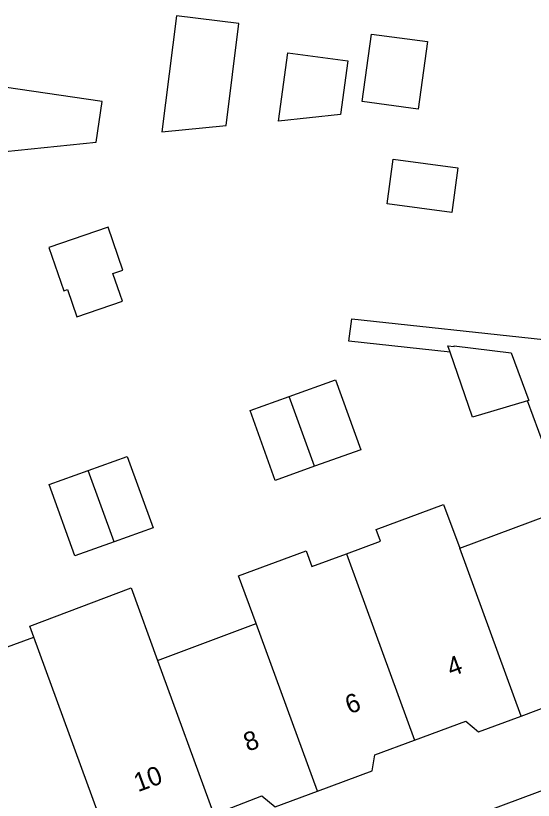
# Model space of a CAD drawing. Extents: x 161258 to 161838, y 380836 to 381727.
# Drawn here: x 161670.25 to 161697.93, y 381501.61 to 381543.54 of the extents above; entities that cross this region are included whole.
import ezdxf

# ---------------------------------------------------------------- set-up
doc = ezdxf.new("R2010")
doc.units = 0
for name, color, linetype in [('IMGEO_Pand', 7, 'Continuous'), ('IMGEO_Pand_nummerreeks', 7, 'Continuous'), ('IMGEO_Voetpad_open', 7, 'Continuous')]:
    doc.layers.add(name, color=color, linetype=linetype)

msp = doc.modelspace()

# ---------------------------------------------------------------- linework, layer by layer
at = {"layer": 'IMGEO_Pand'}
for points in [[(161682.189, 381543.121), (161678.843, 381543.541), (161678.064, 381537.338), (161681.504, 381537.668), (161682.189, 381543.121)], [(161689.275, 381542.561), (161692.27, 381542.154), (161691.781, 381538.551), (161688.786, 381538.958), (161689.275, 381542.561)], [(161684.314, 381537.902), (161684.81, 381541.557), (161688.018, 381541.122), (161687.629, 381538.26), (161684.314, 381537.902)], [(161668.145, 381539.932), (161667.583, 381536.076), (161674.562, 381536.774), (161674.879, 381538.951), (161668.145, 381539.932)], [(161690.441, 381535.882), (161693.901, 381535.411), (161693.576, 381533.016), (161690.115, 381533.486), (161690.441, 381535.882)], [(161675.193, 381532.243), (161672.027, 381531.159), (161672.822, 381528.837), (161673.02, 381528.905), (161673.519, 381527.446), (161675.96, 381528.282), (161675.836, 381528.643), (161675.452, 381529.767), (161675.978, 381529.947), (161675.193, 381532.243)], [(161693.486, 381525.558), (161693.369, 381525.897), (161693.692, 381525.857), (161693.697, 381525.897), (161696.744, 381525.525), (161697.696, 381522.976), (161697.617, 381522.953)], [(161697.617, 381522.953), (161694.683, 381522.091), (161693.486, 381525.558)], [(161684.874, 381523.19), (161687.357, 381524.081), (161688.7, 381520.345), (161686.236, 381519.46)], [(161686.236, 381519.46), (161684.127, 381518.703), (161682.784, 381522.439), (161684.874, 381523.19)], [(161686.236, 381519.46), (161684.874, 381523.19)], [(161674.127, 381519.24), (161676.211, 381519.989), (161677.604, 381516.178), (161675.519, 381515.43)], [(161675.519, 381515.43), (161673.41, 381514.673), (161672.038, 381518.49), (161674.127, 381519.24)], [(161675.519, 381515.43), (161674.127, 381519.24)], [(161687.935, 381514.779), (161689.755, 381515.455), (161689.525, 381516.074), (161693.135, 381517.414), (161693.998, 381515.089)], [(161693.998, 381515.089), (161699.745, 381517.223)], [(161683.119, 381511.049), (161682.172, 381513.599), (161685.781, 381514.939), (161686.095, 381514.095), (161687.935, 381514.779)], [(161697.277, 381506.112), (161693.998, 381515.089)], [(161687.935, 381514.779), (161688.569, 381513.073), (161691.583, 381504.821)], [(161671.22, 381510.325), (161671.004, 381510.916), (161676.417, 381512.97), (161677.836, 381509.087)], [(161677.836, 381509.087), (161683.119, 381511.049)], [(161686.389, 381502.096), (161683.119, 381511.049)], [(161666.051, 381507.805), (161665.848, 381508.363), (161671.22, 381510.325)], [(161675.66, 381498.173), (161674.992, 381500), (161671.22, 381510.325)], [(161677.836, 381509.087), (161680.846, 381500.847)], [(161697.277, 381506.112), (161700.213, 381507.202), (161700.352, 381508.018), (161702.823, 381508.935)], [(161691.583, 381504.821), (161694.323, 381505.839), (161695.01, 381505.27), (161697.277, 381506.112)], [(161686.389, 381502.096), (161689.31, 381503.181), (161689.454, 381504.03), (161691.583, 381504.821)], [(161680.846, 381500.847), (161683.416, 381501.839), (161684.123, 381501.254), (161686.389, 381502.096)]]:
    msp.add_lwpolyline(points, dxfattribs=at)
at = {"layer": 'IMGEO_Voetpad_open'}
for points in [[(161693.486, 381525.558), (161688.074, 381526.15), (161688.236, 381527.342), (161698.47, 381526.241)], [(161699.745, 381517.223), (161697.617, 381522.953)], [(161704.512, 381504.387), (161692.684, 381500), (161641.589, 381481.048)]]:
    msp.add_lwpolyline(points, dxfattribs=at)

# ---------------------------------------------------------------- texts
at = {"layer": 'IMGEO_Pand_nummerreeks'}
for s, p in [('4', (161693.536, 381508.201)), ('6', (161688.097, 381506.199)), ('8', (161682.661, 381504.198)), ('10', (161676.79, 381502.038))]:
    msp.add_text(s, height=1, rotation=20.2099, dxfattribs=at).set_placement(p)

doc.saveas('drawing.dxf')
